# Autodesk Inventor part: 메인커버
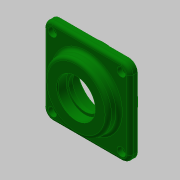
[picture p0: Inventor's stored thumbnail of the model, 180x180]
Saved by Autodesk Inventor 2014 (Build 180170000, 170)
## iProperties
Created: 2018-09
Part Number: 메인커버
Material: 일반
Document SubType Name: Modeling
Designer: mduedu
Density: 1 g/cm^3
Appearance: 진녹색
Mass: 65.8536 g
Surface Area: 197.883 cm^2
Volume: 65.8536 cm^3
Author: mduedu
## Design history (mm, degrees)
sketch "스케치1"
  geometry: L1 (-40, -40)-(40, -40); L2 (40, -40)-(40, 40); L3 (40, 40)-(-40, 40); L4 (-40, 40)-(-40, -40); L5 (-40, -40)-(40, 40); L6 (40, -40)-(-40, 40); 1 further point
  constraints: 12 end point, 2 midpoint, 2 parallel, 1 horizontal, 1 perpendicular
  dimensions: "d0" = 80 distance of L3.end L2.end; "d1" = 80 distance of L2.end L1.end
extrude "돌출1" new body sketch "스케치1" distance "d2" = 7; taper "d3" = 0 deg
sketch "스케치2"
  geometry: C1 r 30 at (0, 0); 1 further point
  constraints: 1 centre point, 1 coincident
  dimensions: "d4" = 60 diameter of C1
extrude "돌출2" join sketch "스케치2" distance "d5" = 10; taper "d6" = 0 deg
sketch "스케치3"
  geometry: C1 r 32.5 at (0, 0); 1 further point
  constraints: 1 centre point, 1 coincident
  dimensions: "d7" = 65 diameter of C1
extrude "돌출3" join sketch "스케치3" distance "d8" = 9; taper "d9" = 0 deg
sketch "스케치4"
  geometry: L1 (-32.5, -9)-(32.5, -9) reference; L2 (30, 17)-(-30, 17) reference; L3 (0, 17)-(0, -9); L4 (0, -9)-(23.5, -9); L5 (23.5, -9)-(23.5, 5); L6 (23.5, 5)-(0, 5); L7 (0, 5)-(0, -9); L8 (0, 5)-(15, 5); L9 (15, 5)-(15, 8.7); L10 (15, 8.7)-(0, 8.7); L11 (0, 8.7)-(0, 5); L12 (0, 8.7)-(17.5, 8.7); L13 (17.5, 8.7)-(17.5, 17); L14 (17.5, 17)-(0, 17); L15 (0, 17)-(0, 8.7); 1 further point
  constraints: 26 end point, 6 parallel, 3 horizontal, 3 perpendicular, 2 midpoint, 1 point on line
  dimensions: "d10" = 14 distance of L4.end L5.end; "d12" = 8.3 distance of L12.end L13.end; "d13" = 35 diameter of L13 L3; "d14" = 30 diameter of L9 L3; "d15" = 47 diameter of L5 L3
revolve "회전1" sketch "스케치4" stored, may be unused: angle "d16" = 90 deg
fillet "모깎기1" dims "d17" = 8
fillet "모깎기2" dims "d18" = 3
fillet "모깎기3" dims "d19" = 3
chamfer "모따기1" distance "d20" = 0.8; stored, may be unused: second distance "d21" = 2, angle "d22" = 30 deg
chamfer "모따기2" distance "d23" = 1; stored, may be unused: second distance "d24" = 2, angle "d25" = 30 deg
fillet "모깎기4" dims "d26" = 0.3
sketch "스케치5"
  geometry: A1 r 8 centre (-32, 32) between (-32, 40) and (-40, 32) reference; A2 r 8 centre (-32, -32) between (-40, -32) and (-32, -40) reference; A3 r 8 centre (32, -32) between (32, -40) and (40, -32) reference; A4 r 8 centre (32, 32) between (40, 32) and (32, 40) reference; 5 further points
  constraints: 4 coincident
hole "구멍1" sketch "스케치5" at (-32, 32), (32, 32), (32, -32), (-32, -32) diameter "d27" = 4.5; stored, may be unused: countersink angle "d31" = 90 deg, drill point angle "d33" = 118 deg; dims "d28" = 6, "d29" = 8, "d30" = 4.4, "d32" = 8
node "솔리드1"
